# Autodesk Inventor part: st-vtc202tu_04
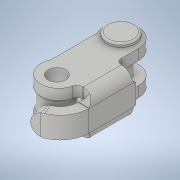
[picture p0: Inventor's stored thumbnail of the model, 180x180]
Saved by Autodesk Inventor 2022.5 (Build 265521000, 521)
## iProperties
Created: 2021-08
Part Number: st-vtc202tu_04
Material: 一般
Document SubType Name: Modeling
Designer: ImaoCorp
Density: 1 g/cm^3
Appearance: 既定
Author: ImaoCorp
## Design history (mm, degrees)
feature "st-vtc202tu_04"
node "ソリッド1"
